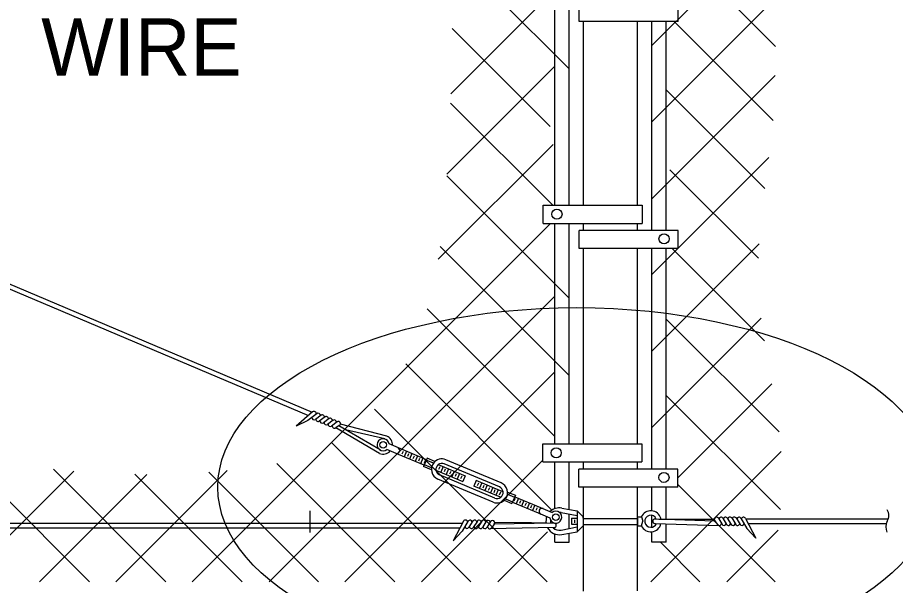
# Model space of a CAD drawing. Extents: x 99862 to 104211, y 98939 to 105076.
# Drawn here: x 101985.8 to 102230.4, y 100337.9 to 100496.1 of the extents above; entities that cross this region are included whole.
import ezdxf

# ---------------------------------------------------------------- set-up
doc = ezdxf.new("R2010")
doc.units = 0
for name, color, linetype in [('Level 11', 7, 'Continuous'), ('Level 2', 7, 'Continuous'), ('Level 20', 7, 'Continuous'), ('Level 4', 7, 'Continuous'), ('Level 7', 7, 'Continuous')]:
    doc.layers.add(name, color=color, linetype=linetype)

msp = doc.modelspace()

# ---------------------------------------------------------------- linework, layer by layer
at = {"layer": 'Level 11'}
msp.add_ellipse((102141.61, 100365.28), major_axis=(100, 0), ratio=0.5, dxfattribs=at)
at = {"layer": 'Level 2'}
for p, q in [((101478.62, 100635.63), (102067.94, 100386.16)), ((101478.72, 100634.17), (102066.84, 100385.21)), ((102068.02, 100386.23), (102063.46, 100382.3)), ((102069.25, 100385.8), (102066.69, 100383.85)), ((102070.39, 100385.35), (102068.8, 100384.15)), ((102066.69, 100383.85), (102063.46, 100382.3)), ((102071.52, 100384.89), (102069.84, 100383.64)), ((102072.62, 100384.42), (102071.03, 100383.22)), ((102073.71, 100383.94), (102072.14, 100382.74)), ((102074.82, 100383.47), (102073.28, 100382.29)), ((102075.44, 100382.44), (102074.48, 100381.83)), ((102086.65, 100374.68), (102074.48, 100381.83)), ((102086.83, 100375.66), (102075.3, 100382.35)), ((102088.69, 100379.52), (102075.75, 100382.81)), ((102088.13, 100378.7), (102077.17, 100381.27)), ((102091.96, 100374.4), (102088.68, 100375.77)), ((102092.6, 100375.94), (102089.32, 100377.31)), ((102099.76, 100372.93), (102092.6, 100375.94)), ((102099.12, 100371.4), (102091.96, 100374.4)), ((102093.21, 100375.23), (102092.89, 100374.46)), ((102094.14, 100375.29), (102093.49, 100373.75)), ((102094.75, 100374.59), (102094.42, 100373.82)), ((102095.67, 100374.65), (102095.03, 100373.11)), ((102096.28, 100373.94), (102095.96, 100373.17)), ((102097.21, 100374), (102096.57, 100372.47)), ((102097.82, 100373.3), (102097.5, 100372.53)), ((102098.75, 100373.36), (102098.1, 100371.82)), ((102099.92, 100373.32), (102098.96, 100371.01)), ((102102.1, 100372.4), (102099.92, 100373.32)), ((102101.14, 100370.1), (102098.96, 100371.01)), ((102099.36, 100372.65), (102099.03, 100371.88)), ((102103.04, 100371.56), (102110.52, 100368.43)), ((102103.44, 100370.94), (102103.12, 100370.17)), ((102104.37, 100371), (102103.72, 100369.47)), ((102120.06, 100365.33), (102104.69, 100371.77)), ((102120.54, 100366.48), (102105.18, 100372.92)), ((102102.4, 100370.02), (102109.87, 100366.89)), ((102118.77, 100362.25), (102103.39, 100368.7)), ((102104.98, 100370.3), (102104.65, 100369.53)), ((102105.91, 100370.36), (102105.26, 100368.82)), ((102106.51, 100369.65), (102106.19, 100368.88)), ((102107.44, 100369.71), (102106.8, 100368.18)), ((102108.05, 100369.01), (102107.73, 100368.24)), ((102108.98, 100369.07), (102108.33, 100367.53)), ((102109.59, 100368.36), (102109.26, 100367.6)), ((102110.52, 100368.43), (102109.87, 100366.89)), ((102118.29, 100361.1), (102102.91, 100367.55)), ((102113.59, 100367.14), (102112.94, 100365.6)), ((102121.06, 100364), (102113.59, 100367.14)), ((102114.2, 100366.43), (102113.87, 100365.66)), ((102115.13, 100366.49), (102114.48, 100364.96)), ((102115.73, 100365.79), (102115.41, 100365.02)), ((102116.66, 100365.85), (102116.02, 100364.31)), ((102120.42, 100362.47), (102112.94, 100365.6)), ((102117.27, 100365.14), (102116.95, 100364.37)), ((102118.2, 100365.21), (102117.55, 100363.67)), ((102118.81, 100364.5), (102118.48, 100363.73)), ((102119.74, 100364.56), (102119.09, 100363.02)), ((102120.34, 100363.85), (102120.02, 100363.09)), ((102122.33, 100363.93), (102124.51, 100363.01)), ((102121.36, 100361.62), (102123.54, 100360.71)), ((102124.51, 100363.01), (102123.54, 100360.71)), ((102123.71, 100361.09), (102130.86, 100358.09)), ((102124.43, 100362.14), (102124.1, 100361.37)), ((102124.35, 100362.63), (102131.5, 100359.63)), ((102125.36, 100362.2), (102124.71, 100360.67)), ((102125.96, 100361.5), (102125.64, 100360.73)), ((102126.89, 100361.56), (102126.25, 100360.02)), ((102127.5, 100360.85), (102127.18, 100360.09)), ((102128.43, 100360.92), (102127.78, 100359.38)), ((102129.04, 100360.21), (102128.71, 100359.44)), ((102129.97, 100360.27), (102129.32, 100358.74)), ((102130.57, 100359.57), (102130.25, 100358.8)), ((102131.48, 100359.64), (102134.76, 100358.26)), ((102137.45, 100359.47), (102141.77, 100358.7)), ((102141.77, 100358.7), (102143.45, 100357.01)), ((102141.77, 100358.7), (102141.77, 100352.86)), ((102130.84, 100358.1), (102134.12, 100356.72)), ((102137.27, 100358.23), (102141.77, 100357.35)), ((102140.12, 100356.61), (102140.12, 100354.94)), ((102140.12, 100356.61), (102141.77, 100356.61)), ((102140.95, 100356.19), (102140.95, 100355.36)), ((102143.45, 100356.61), (102143.45, 100354.94)), ((102143.47, 100356.53), (102158.55, 100356.53)), ((102158.55, 100356.61), (102158.55, 100354.94)), ((102159.62, 100357.03), (102160, 100355.78)), ((102163.42, 100356.42), (102180.09, 100355.91)), ((102164.45, 100356.39), (102169.72, 100356.39)), ((102169.72, 100356.39), (102179.94, 100356.39)), ((102181.1, 100356.65), (102182.1, 100354.92)), ((102182.34, 100356.66), (102183.36, 100354.89)), ((102183.57, 100356.69), (102184.62, 100354.91)), ((102184.81, 100356.71), (102185.92, 100354.84)), ((102186.06, 100356.7), (102187.11, 100354.92)), ((102187.33, 100356.67), (102189, 100353.81)), ((102188.68, 100356.6), (102191.48, 100351.05)), ((102188.76, 100356.44), (102228.44, 100356.44)), ((101480.26, 100355.34), (102109.78, 100355.28)), ((101480.93, 100354.04), (102109.1, 100353.98)), ((102110.05, 100355.8), (102107.17, 100350.29)), ((102111.4, 100355.86), (102109.68, 100353.02)), ((102112.66, 100355.86), (102111.59, 100354.11)), ((102113.92, 100355.85), (102112.78, 100354.01)), ((102115.16, 100355.82), (102114.08, 100354.06)), ((102116.39, 100355.78), (102115.34, 100354.02)), ((102117.63, 100355.74), (102116.6, 100354.03)), ((102135.35, 100354.01), (102117.52, 100353.72)), ((102118.62, 100354.99), (102117.93, 100354.04)), ((102135.3, 100355.25), (102118.62, 100354.99)), ((102129, 100355.31), (102118.78, 100355.46)), ((102133.08, 100355.26), (102129, 100355.31)), ((102137.27, 100353.32), (102141.77, 100354.21)), ((102140.12, 100354.94), (102141.77, 100354.94)), ((102141.77, 100352.86), (102143.45, 100354.54)), ((102143.45, 100355.78), (102143.45, 100354.94)), ((102143.47, 100354.86), (102158.55, 100354.86)), ((102159.62, 100354.53), (102160, 100355.78)), ((102163.35, 100355.17), (102181.17, 100354.63)), ((102180.09, 100355.91), (102180.77, 100354.95)), ((102189, 100353.81), (102191.48, 100351.05)), ((102189.41, 100355.14), (102227.87, 100355.14)), ((102109.68, 100353.02), (102107.17, 100350.29)), ((102137.45, 100352.09), (102141.77, 100352.86))]:
    msp.add_line(p, q, dxfattribs=at)
for points in [[(102101.17, 100370.7), (102099.18, 100371.54)], [(102101.7, 100371.96), (102099.7, 100372.79)], [(102122.3, 100363.32), (102124.29, 100362.49)], [(102121.77, 100362.07), (102123.76, 100361.23)], [(102143.45, 100356.61), (102143.45, 100357.01)], [(102158.55, 100356.61), (102158.55, 100357.03), (102159.62, 100357.03)], [(102143.45, 100354.94), (102143.45, 100354.54)], [(102158.55, 100354.94), (102158.55, 100354.53), (102159.62, 100354.53)]]:
    msp.add_lwpolyline(points, dxfattribs=at)
for centre in [(102087.67, 100377.1), (102135.77, 100356.93)]:
    msp.add_circle(centre, 0.916, dxfattribs=at)
for centre, radius, start, end in [((102068.41, 100385.77), 0.605, 343.9461, 130.7849), ((102069.58, 100385.29), 0.605, 350.2196, 131.8424), ((102070.7, 100384.83), 0.605, 350.1408, 133.5806), ((102068.43, 100384.64), 0.605, 172.2413, 306.9056), ((102069.54, 100384.17), 0.605, 170.8431, 314.3723), ((102070.66, 100383.7), 0.605, 170.2202, 307.0153), ((102071.79, 100383.24), 0.605, 169.3193, 309.7762), ((102071.81, 100384.36), 0.605, 350.2605, 134.3723), ((102072.91, 100382.77), 0.605, 170.3925, 307.5196), ((102072.93, 100383.9), 0.605, 350.3925, 133.1108), ((102074.05, 100383.44), 0.605, 350.4501, 131.0552), ((102075.17, 100382.98), 0.605, 296.5031, 129.3869), ((102074.09, 100382.29), 0.605, 162.8165, 310.7648), ((102087.67, 100377.1), 1.67, 7.2561, 307.2561), ((102087.67, 100377.1), 2.63, 355.7607, 67.2252), ((102091.49, 100375.5), 0.833, 247.2561, 67.2561), ((102087.67, 100377.1), 2.63, 247.2252, 318.7515), ((102104.05, 100370.23), 2.92, 67.2542, 143.728), ((102104.05, 100370.23), 2.92, 141.4089, 247.2561), ((102104.05, 100370.23), 1.67, 127.2519, 247.2561), ((102104.05, 100370.23), 1.67, 67.2543, 127.245), ((102119.42, 100363.79), 2.92, 323.3513, 67.258), ((102119.42, 100363.79), 1.67, 307.2561, 67.2579), ((102119.42, 100363.79), 2.92, 247.2561, 323.7314), ((102119.42, 100363.79), 1.67, 247.2561, 307.2561), ((102131.95, 100358.54), 0.833, 67.2561, 247.2561), ((102135.77, 100356.93), 1.67, 187.2561, 127.2561), ((102136.79, 100355.78), 3.75, 79.8887, 133.5337), ((102162.25, 100355.78), 2.92, 16.6015, 154.6231), ((102225.38, 100357.39), 3.2, 330, 30), ((102110.6, 100355.51), 0.625, 5.5723, 152.411), ((102111.91, 100355.49), 0.625, 11.8457, 153.4685), ((102113.16, 100355.48), 0.625, 11.7669, 155.2067), ((102114.41, 100355.46), 0.625, 11.8866, 155.9985), ((102115.65, 100355.44), 0.625, 12.0186, 154.7369), ((102116.9, 100355.42), 0.625, 12.0762, 152.6813), ((102118.15, 100355.4), 0.625, 318.1293, 151.013), ((102136.79, 100355.78), 3.75, 159.6712, 188.5498), ((102136.79, 100355.78), 2.5, 171.9055, 192.0825), ((102136.79, 100355.78), 2.5, 78.9793, 90.6287), ((102162.25, 100355.78), 1.67, 22.184, 270), ((102163.42, 100355.79), 0.626, 90, 264.3449), ((102162.25, 100355.78), 2.92, 11.6561, 16.6015), ((102180.57, 100356.32), 0.625, 28.1557, 221.0394), ((102181.82, 100356.32), 0.625, 26.4874, 167.0925), ((102183.07, 100356.32), 0.625, 24.4318, 167.1501), ((102184.32, 100356.32), 0.625, 23.1702, 167.2821), ((102185.57, 100356.32), 0.625, 23.962, 167.4018), ((102186.82, 100356.32), 0.625, 25.7002, 167.323), ((102188.12, 100356.32), 0.625, 26.7577, 173.5964), ((102111.05, 100354.43), 0.625, 193.8674, 328.5317), ((102112.3, 100354.4), 0.625, 192.4692, 335.9985), ((102113.55, 100354.38), 0.625, 191.8464, 328.6414), ((102114.81, 100354.37), 0.625, 190.9454, 331.4023), ((102116.07, 100354.35), 0.625, 192.0186, 329.1458), ((102117.38, 100354.33), 0.625, 184.4426, 332.3909), ((102136.79, 100355.78), 3.75, 209.159, 280.1113), ((102136.79, 100355.78), 2.5, 225.4238, 281.1362), ((102135.3, 100354.63), 0.626, 274.8238, 89.1687), ((102162.25, 100355.78), 2.92, 205.3769, 346.8985), ((102162.25, 100355.78), 1.67, 270, 338.0986), ((102181.33, 100355.23), 0.625, 206.7778, 354.7261), ((102182.64, 100355.23), 0.625, 210.0229, 347.1501), ((102183.89, 100355.23), 0.625, 207.7664, 348.2233), ((102185.16, 100355.23), 0.625, 210.5273, 347.3224), ((102186.41, 100355.23), 0.625, 203.1702, 346.6995), ((102187.65, 100355.24), 0.625, 210.637, 345.3013), ((102230.92, 100354.19), 3.2, 150, 206.9934)]:
    msp.add_arc(centre, radius, start, end, dxfattribs=at)
at = {"layer": 'Level 4'}
for p, q in [((102162.56, 100488.28), (102194.37, 100520.08)), ((102196.98, 100488.06), (102166.58, 100518.46)), ((102139.49, 100481.77), (102106.38, 100514.88)), ((102106.55, 100474.86), (102133.68, 100501.98)), ((102162.56, 100467.04), (102196.21, 100500.68)), ((102134.23, 100465.74), (102106.92, 100493.06)), ((102196.35, 100467.4), (102168.79, 100494.97)), ((102105.42, 100452.46), (102135.47, 100482.51)), ((102162.56, 100445.58), (102196.9, 100479.9)), ((102194.02, 100448.48), (102166.58, 100475.92)), ((102134.93, 100443.78), (102106.45, 100472.25)), ((102103.05, 100428.77), (102135.01, 100460.73)), ((102162.56, 100424.48), (102195.14, 100457.06)), ((102139.49, 100417.94), (102105.4, 100452.03)), ((102192.23, 100429.02), (102167.55, 100453.71)), ((102034.47, 100338.95), (102134.29, 100438.76)), ((102139.49, 100396.41), (102103.6, 100432.35)), ((102162.56, 100403.18), (102192.43, 100433.05)), ((102193.9, 100406.07), (102168.23, 100431.74)), ((102055.87, 100338.95), (102135.47, 100418.51)), ((102135.47, 100379.39), (102099.93, 100414.94)), ((102162.56, 100381.9), (102193.03, 100412.36)), ((102197.99, 100380.71), (102166.58, 100412.12)), ((102134.7, 100358.89), (102093.97, 100399.63)), ((102077.03, 100338.95), (102135.47, 100397.39)), ((102169.81, 100367.89), (102195.94, 100394.02)), ((102198.4, 100359.03), (102166.58, 100390.84)), ((102133.37, 100338.95), (102085.26, 100387.05)), ((102112.13, 100338.95), (102073.42, 100377.67)), ((102005.88, 100338.95), (101971.18, 100373.65)), ((102162.25, 100338.95), (102198.55, 100375.23)), ((102090.9, 100338.95), (102058.01, 100371.85)), ((102098.32, 100338.95), (102132.19, 100372.81)), ((101970.64, 100338.95), (102001.45, 100369.76)), ((101991.91, 100338.95), (102021.81, 100368.84)), ((102027.15, 100338.95), (101995.79, 100370.3)), ((102013.21, 100338.95), (102044.19, 100369.92)), ((102048.43, 100338.95), (102018.51, 100368.87)), ((102069.67, 100338.95), (102039.15, 100369.47)), ((102196.89, 100338.95), (102169.81, 100366.06)), ((102067.36, 100352.61), (102067.36, 100358.65)), ((102119.6, 100338.95), (102133.47, 100352.82)), ((102183.41, 100338.95), (102197.78, 100353.31)), ((102175.92, 100338.95), (102164.95, 100349.92))]:
    msp.add_line(p, q, dxfattribs=at)
at = {"layer": 'Level 7'}
for p, q in [((102135.47, 100443.78), (102135.47, 100501.98)), ((102139.49, 100443.78), (102139.49, 100501.98)), ((102142.25, 100494.97), (102142.25, 100499.98)), ((102169.84, 100494.97), (102169.84, 100499.98)), ((102169.84, 100494.97), (102142.25, 100494.97)), ((102143.51, 100482.55), (102143.51, 100494.97)), ((102158.55, 100482.55), (102158.55, 100494.97)), ((102162.56, 100436.76), (102162.56, 100494.97)), ((102166.58, 100436.76), (102166.58, 100494.97)), ((102143.51, 100443.78), (102143.51, 100482.55)), ((102158.55, 100443.78), (102158.55, 100482.55)), ((102132.22, 100443.78), (102159.81, 100443.78)), ((102132.22, 100438.76), (102132.22, 100443.78)), ((102159.81, 100443.78), (102159.81, 100438.76)), ((102132.22, 100438.76), (102159.81, 100438.76)), ((102135.47, 100377.31), (102135.47, 100438.6)), ((102139.49, 100377.31), (102139.49, 100438.76)), ((102169.84, 100436.76), (102142.25, 100436.76)), ((102142.25, 100431.74), (102142.25, 100436.76)), ((102143.51, 100436.73), (102143.51, 100438.73)), ((102158.55, 100436.73), (102158.55, 100438.73)), ((102169.84, 100431.74), (102169.84, 100436.76)), ((102169.84, 100431.74), (102142.25, 100431.74)), ((102143.51, 100377.31), (102143.51, 100431.74)), ((102158.55, 100409.57), (102158.55, 100431.74)), ((102158.55, 100377.31), (102158.55, 100431.74)), ((102162.56, 100370.29), (102162.56, 100431.74)), ((102166.58, 100370.29), (102166.58, 100431.74)), ((102132.19, 100377.31), (102159.78, 100377.31)), ((102132.19, 100372.3), (102132.19, 100377.31)), ((102159.78, 100377.31), (102159.78, 100372.3)), ((102132.19, 100372.3), (102159.78, 100372.3)), ((102135.47, 100359.29), (102135.47, 100372.3)), ((102139.49, 100359.1), (102139.49, 100372.3)), ((102143.51, 100370.26), (102143.51, 100372.26)), ((102158.55, 100370.26), (102158.55, 100372.26)), ((102169.81, 100370.29), (102142.22, 100370.29)), ((102142.22, 100365.28), (102142.22, 100370.29)), ((102169.81, 100365.28), (102169.81, 100370.29)), ((102169.81, 100365.28), (102142.22, 100365.28)), ((102143.51, 100336.28), (102143.51, 100365.28)), ((102158.55, 100336.41), (102158.55, 100365.28)), ((102162.56, 100358.68), (102162.56, 100365.28)), ((102166.58, 100356.39), (102166.58, 100365.28)), ((102139.49, 100353.76), (102139.49, 100357.8)), ((102162.56, 100354.14), (102162.56, 100357.41)), ((102135.47, 100353.65), (102135.47, 100354.03)), ((102166.58, 100349.92), (102166.58, 100355.01)), ((102135.47, 100349.92), (102135.47, 100352.27)), ((102139.49, 100349.92), (102139.49, 100352.45)), ((102162.56, 100349.92), (102162.56, 100352.88)), ((102135.47, 100349.92), (102139.49, 100349.92)), ((102166.58, 100349.92), (102162.56, 100349.92))]:
    msp.add_line(p, q, dxfattribs=at)
for centre in [(102136.11, 100441.32), (102165.94, 100434.46), (102135.91, 100374.86), (102165.92, 100368)]:
    msp.add_circle(centre, 1.41, dxfattribs=at)

# ---------------------------------------------------------------- texts
at = {"layer": 'Level 20'}
msp.add_text('WIRE', height=16, rotation=360, dxfattribs=at).set_placement((101992.39, 100479.88))

doc.saveas('drawing.dxf')
